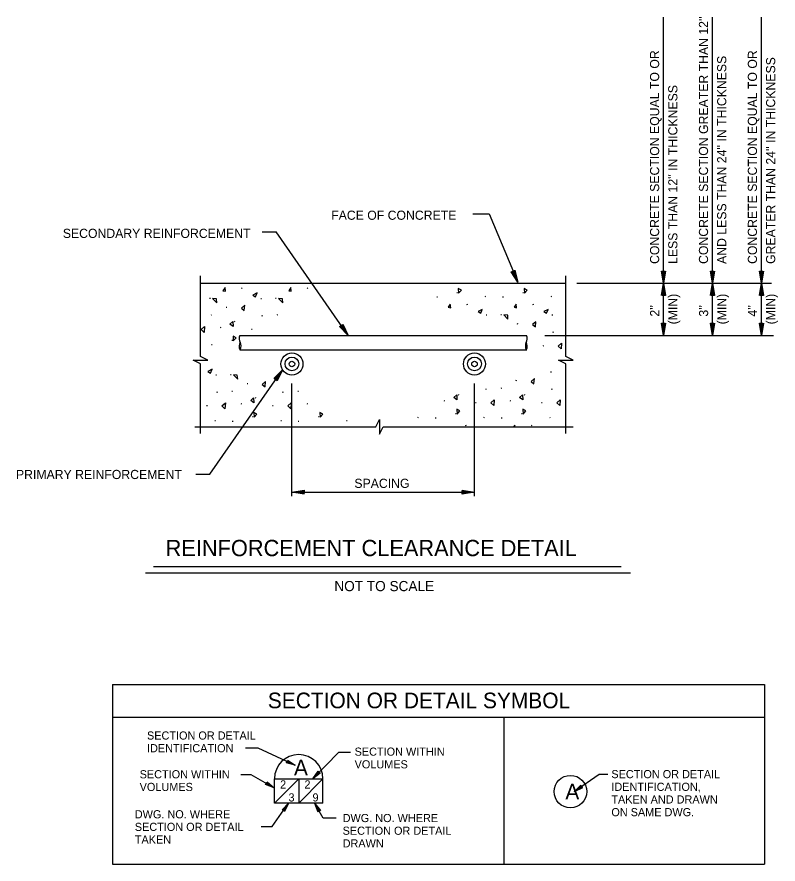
# Model space of a CAD drawing. Extents: x 22369.62 to 22376.4, y 22369.62 to 22372.46.
# Drawn here: x 22375.429 to 22376.402, y 22369.902 to 22370.985 of the extents above; entities that cross this region are included whole.
import ezdxf

# ---------------------------------------------------------------- set-up
doc = ezdxf.new("R2010")
doc.units = 0
for name, color, linetype in [('Default', 7, 'Continuous'), ('Level 1', 7, 'Continuous'), ('Level 10', 7, 'Continuous'), ('Level 2', 7, 'Continuous'), ('Level 22', 7, 'Continuous'), ('Level 3', 7, 'Continuous'), ('Level 4', 7, 'Continuous'), ('Level 50', 7, 'Continuous'), ('Level 7', 7, 'Continuous'), ('Level 8', 7, 'Continuous')]:
    doc.layers.add(name, color=color, linetype=linetype)

msp = doc.modelspace()

# ---------------------------------------------------------------- linework, layer by layer
at = {"layer": 'Default'}
for p, q in [((22375.7173, 22370.6384), (22375.7163, 22370.6379)), ((22375.8014, 22370.6384), (22375.8004, 22370.6379)), ((22375.967, 22370.6265), (22375.9659, 22370.6265)), ((22375.9927, 22370.6321), (22375.9918, 22370.6322)), ((22376.0288, 22370.6272), (22376.0279, 22370.6274)), ((22376.0512, 22370.6265), (22376.0501, 22370.6265)), ((22376.0768, 22370.6321), (22376.076, 22370.6322)), ((22376.1129, 22370.6272), (22376.1121, 22370.6274)), ((22375.6767, 22370.625), (22375.6756, 22370.625)), ((22375.7422, 22370.6246), (22375.7411, 22370.6246)), ((22375.7609, 22370.625), (22375.7598, 22370.625)), ((22376.0052, 22370.6174), (22376.0042, 22370.6169)), ((22376.0894, 22370.6174), (22376.0884, 22370.6169)), ((22375.6979, 22370.6133), (22375.6968, 22370.6135)), ((22375.6783, 22370.6039), (22375.6775, 22370.6036)), ((22375.7085, 22370.5951), (22375.7076, 22370.5956)), ((22375.7431, 22370.6028), (22375.742, 22370.6025)), ((22375.7625, 22370.6039), (22375.7617, 22370.6036)), ((22376.0301, 22370.6036), (22376.029, 22370.6036)), ((22376.0488, 22370.604), (22376.0477, 22370.604)), ((22376.1143, 22370.6036), (22376.1132, 22370.6036)), ((22375.6904, 22370.5873), (22375.6895, 22370.5877)), ((22375.7303, 22370.5853), (22375.7294, 22370.5852)), ((22376.07, 22370.5923), (22376.0689, 22370.5925)), ((22376.1152, 22370.5818), (22376.1141, 22370.5815)), ((22375.6791, 22370.5656), (22375.678, 22370.5656)), ((22375.7048, 22370.5711), (22375.7039, 22370.5712)), ((22376.1024, 22370.5643), (22376.1015, 22370.5642)), ((22376.1125, 22370.531), (22376.1114, 22370.531)), ((22376.1309, 22370.5314), (22376.1301, 22370.5314)), ((22375.6847, 22370.527), (22375.6835, 22370.527)), ((22375.7033, 22370.5274), (22375.7023, 22370.5274)), ((22376.0682, 22370.5198), (22376.0671, 22370.52)), ((22375.7245, 22370.5158), (22375.7235, 22370.516)), ((22376.0292, 22370.5092), (22376.0281, 22370.5089)), ((22376.0486, 22370.5103), (22376.0478, 22370.51)), ((22376.1134, 22370.5092), (22376.1123, 22370.5089)), ((22375.6856, 22370.5052), (22375.6844, 22370.5049)), ((22375.705, 22370.5063), (22375.7042, 22370.506)), ((22375.7351, 22370.4975), (22375.7342, 22370.4981)), ((22375.7697, 22370.5052), (22375.7686, 22370.5049)), ((22375.7891, 22370.5063), (22375.7883, 22370.506)), ((22375.9946, 22370.5015), (22375.9937, 22370.5021)), ((22376.0788, 22370.5015), (22376.0779, 22370.5021)), ((22375.6728, 22370.4878), (22375.6719, 22370.4877)), ((22375.717, 22370.4898), (22375.7161, 22370.4902)), ((22375.757, 22370.4878), (22375.7561, 22370.4877)), ((22375.8012, 22370.4898), (22375.8003, 22370.4902)), ((22375.9765, 22370.4938), (22375.9756, 22370.4942)), ((22376.0165, 22370.4918), (22376.0155, 22370.4917)), ((22376.0606, 22370.4938), (22376.0598, 22370.4942)), ((22376.1006, 22370.4918), (22376.0997, 22370.4917)), ((22375.9909, 22370.4776), (22375.99, 22370.4776)), ((22376.075, 22370.4776), (22376.0742, 22370.4776)), ((22375.6833, 22370.4687), (22375.6825, 22370.4688)), ((22375.7058, 22370.468), (22375.7046, 22370.468)), ((22375.7314, 22370.4736), (22375.7306, 22370.4736)), ((22375.7675, 22370.4687), (22375.7667, 22370.4688)), ((22375.7899, 22370.468), (22375.7888, 22370.468)), ((22375.8156, 22370.4736), (22375.8147, 22370.4736)), ((22375.8517, 22370.4687), (22375.8508, 22370.4688)), ((22375.9428, 22370.4727), (22375.942, 22370.4728)), ((22375.9652, 22370.472), (22375.9641, 22370.472)), ((22376.027, 22370.4727), (22376.0261, 22370.4728)), ((22376.0494, 22370.472), (22376.0483, 22370.472)), ((22376.1111, 22370.4727), (22376.1103, 22370.4728)), ((22376.0034, 22370.4629), (22376.0024, 22370.4624)), ((22376.0876, 22370.4629), (22376.0866, 22370.4624))]:
    msp.add_line(p, q, dxfattribs=at)
for points in [[(22375.6959, 22370.6342), (22375.6954, 22370.6388), (22375.6928, 22370.6349)], [(22375.7801, 22370.6342), (22375.7795, 22370.6388), (22375.777, 22370.6349)], [(22375.9939, 22370.6318), (22375.9974, 22370.6358), (22375.9935, 22370.6379)], [(22376.0781, 22370.6318), (22376.0816, 22370.6358), (22376.0776, 22370.6379)], [(22375.7343, 22370.627), (22375.7363, 22370.6321), (22375.7308, 22370.6294)], [(22375.6845, 22370.6247), (22375.6795, 22370.625), (22375.6849, 22370.6194)], [(22375.7207, 22370.6163), (22375.7164, 22370.6126), (22375.7199, 22370.6096)], [(22375.7687, 22370.6247), (22375.7637, 22370.625), (22375.7691, 22370.6194)], [(22375.9839, 22370.6132), (22375.9833, 22370.6178), (22375.9807, 22370.6139)], [(22376.068, 22370.6132), (22376.0674, 22370.6178), (22376.0649, 22370.6139)], [(22376.0222, 22370.606), (22376.0242, 22370.6111), (22376.0187, 22370.6084)], [(22376.1064, 22370.606), (22376.1084, 22370.6111), (22376.1029, 22370.6084)], [(22375.7056, 22370.5892), (22375.7016, 22370.5922), (22375.7054, 22370.5956)], [(22376.0566, 22370.6037), (22376.0516, 22370.604), (22376.057, 22370.5984)], [(22376.0927, 22370.5953), (22376.0885, 22370.5916), (22376.092, 22370.5886)], [(22375.6687, 22370.5817), (22375.6648, 22370.5852), (22375.6691, 22370.589)], [(22375.706, 22370.5708), (22375.7095, 22370.5748), (22375.7056, 22370.577)], [(22376.1249, 22370.5607), (22376.1211, 22370.5642), (22376.1254, 22370.568)], [(22375.6768, 22370.5295), (22375.6788, 22370.5346), (22375.6733, 22370.5319)], [(22375.7111, 22370.5272), (22375.7061, 22370.5274), (22375.7116, 22370.5219)], [(22375.7473, 22370.5188), (22375.743, 22370.5151), (22375.7466, 22370.5121)], [(22376.0909, 22370.5228), (22376.0867, 22370.519), (22376.0902, 22370.5161)], [(22375.7322, 22370.4916), (22375.7282, 22370.4946), (22375.732, 22370.498)], [(22375.9917, 22370.4956), (22375.9877, 22370.4986), (22375.9915, 22370.502)], [(22376.0758, 22370.4956), (22376.0718, 22370.4986), (22376.0757, 22370.502)], [(22375.6953, 22370.4841), (22375.6915, 22370.4877), (22375.6958, 22370.4915)], [(22375.7795, 22370.4841), (22375.7756, 22370.4877), (22375.7799, 22370.4915)], [(22376.039, 22370.4881), (22376.0351, 22370.4916), (22376.0394, 22370.4955)], [(22376.1231, 22370.4881), (22376.1193, 22370.4916), (22376.1236, 22370.4955)], [(22375.7326, 22370.4733), (22375.7362, 22370.4773), (22375.7322, 22370.4794)], [(22375.8168, 22370.4733), (22375.8203, 22370.4773), (22375.8164, 22370.4794)], [(22375.9921, 22370.4773), (22375.9956, 22370.4813), (22375.9917, 22370.4834)], [(22376.0763, 22370.4773), (22376.0798, 22370.4813), (22376.0758, 22370.4834)]]:
    msp.add_lwpolyline(points, close=True, dxfattribs=at)
msp.add_lwpolyline([(22376.0659, 22370.4609), (22376.0656, 22370.4632), (22376.0641, 22370.4609)], dxfattribs=at)
at = {"layer": 'Level 1'}
for p, q in [((22376.2559, 22370.6444), (22376.2559, 22370.9842)), ((22376.3184, 22370.6444), (22376.3184, 22370.9842)), ((22376.3809, 22370.6444), (22376.3809, 22370.9842)), ((22376.3809, 22370.6444), (22376.3809, 22370.7294)), ((22375.6642, 22370.5508), (22375.6642, 22370.6541)), ((22376.1309, 22370.5508), (22376.1309, 22370.6541)), ((22376.145, 22370.6444), (22376.3938, 22370.6444)), ((22376.2559, 22370.5777), (22376.2559, 22370.6444)), ((22376.3184, 22370.5777), (22376.3184, 22370.6444)), ((22376.3809, 22370.5777), (22376.3809, 22370.6444)), ((22376.1039, 22370.5777), (22376.3962, 22370.5777)), ((22375.6736, 22370.5461), (22375.6642, 22370.5508)), ((22376.1402, 22370.5461), (22376.1309, 22370.5508)), ((22375.6642, 22370.5415), (22375.6548, 22370.5461)), ((22375.6548, 22370.5461), (22375.6736, 22370.5461)), ((22375.6642, 22370.4527), (22375.6642, 22370.5415)), ((22376.1309, 22370.5415), (22376.1215, 22370.5461)), ((22376.1215, 22370.5461), (22376.1402, 22370.5461)), ((22376.1309, 22370.4527), (22376.1309, 22370.5415)), ((22375.7809, 22370.3725), (22375.7809, 22370.5164)), ((22376.0142, 22370.3725), (22376.0142, 22370.5164)), ((22375.888, 22370.4611), (22375.8927, 22370.4704)), ((22375.8927, 22370.4704), (22375.8927, 22370.4517)), ((22375.6569, 22370.4611), (22375.888, 22370.4611)), ((22375.8927, 22370.4517), (22375.8974, 22370.4611)), ((22375.8974, 22370.4611), (22376.1401, 22370.4611)), ((22375.7809, 22370.3777), (22376.0142, 22370.3777)), ((22375.7823, 22370.0301), (22375.7823, 22370.0301)), ((22375.7852, 22370.0288), (22375.7852, 22370.0288)), ((22375.8076, 22370.0115), (22375.8076, 22370.0115)), ((22375.8099, 22370.0138), (22375.8099, 22370.0138)), ((22375.7555, 22370.0016), (22375.7555, 22370.0016)), ((22375.7584, 22370), (22375.7584, 22370)), ((22376.1415, 22369.9949), (22376.1415, 22369.9949)), ((22376.1442, 22369.9968), (22376.1442, 22369.9968)), ((22375.7747, 22369.9777), (22375.7747, 22369.9777)), ((22375.7766, 22369.9804), (22375.7766, 22369.9804)), ((22375.8101, 22369.9799), (22375.8101, 22369.9799)), ((22375.8117, 22369.9771), (22375.8117, 22369.9771))]:
    msp.add_line(p, q, dxfattribs=at)
for points in [[(22375.7214, 22370.0509), (22375.7373, 22370.0509), (22375.7852, 22370.0288)], [(22375.8558, 22370.0451), (22375.8405, 22370.0451), (22375.8076, 22370.0115)], [(22375.7754, 22370.0354), (22375.7852, 22370.0288), (22375.7738, 22370.0319), (22375.7752, 22370.0349), (22375.7823, 22370.0301), (22375.7745, 22370.0323), (22375.7754, 22370.0342), (22375.7794, 22370.0315), (22375.7752, 22370.0326), (22375.7756, 22370.0334), (22375.7765, 22370.0328)], [(22375.8172, 22370.0185), (22375.8076, 22370.0115), (22375.8144, 22370.0212), (22375.8168, 22370.0189), (22375.8099, 22370.0138), (22375.8145, 22370.0204), (22375.816, 22370.0189), (22375.8121, 22370.0161), (22375.8146, 22370.0196), (22375.8152, 22370.019), (22375.8143, 22370.0184)], [(22375.7156, 22370.0169), (22375.7283, 22370.0169), (22375.7584, 22370)], [(22376.1845, 22370.017), (22376.1736, 22370.017), (22376.1415, 22369.9949)], [(22375.7491, 22370.0074), (22375.7584, 22370), (22375.7472, 22370.004), (22375.7489, 22370.0069), (22375.7555, 22370.0016), (22375.748, 22370.0043), (22375.749, 22370.0062), (22375.7528, 22370.0031), (22375.7487, 22370.0046), (22375.7491, 22370.0054), (22375.75, 22370.0047)], [(22376.1523, 22370), (22376.1415, 22369.9949), (22376.1501, 22370.0032), (22376.152, 22370.0004), (22376.1442, 22369.9968), (22376.15, 22370.0024), (22376.1512, 22370.0006), (22376.1468, 22369.9986), (22376.15, 22370.0016), (22376.1505, 22370.0009), (22376.1495, 22370.0004)], [(22375.7417, 22369.9504), (22375.7558, 22369.9504), (22375.7766, 22369.9804)], [(22375.7683, 22369.9719), (22375.7766, 22369.9804), (22375.7715, 22369.9697), (22375.7688, 22369.9716), (22375.7747, 22369.9777), (22375.7713, 22369.9705), (22375.7695, 22369.9717), (22375.773, 22369.9752), (22375.7711, 22369.9712), (22375.7703, 22369.9717), (22375.7711, 22369.9725)], [(22375.8374, 22369.9613), (22375.8208, 22369.9613), (22375.8101, 22369.9799)], [(22375.8143, 22369.9688), (22375.8101, 22369.9799), (22375.8176, 22369.9707), (22375.8147, 22369.9691), (22375.8117, 22369.9771), (22375.8168, 22369.9708), (22375.815, 22369.9698), (22375.8133, 22369.9744), (22375.816, 22369.9709), (22375.8153, 22369.9705), (22375.8149, 22369.9715)]]:
    msp.add_lwpolyline(points, dxfattribs=at)
at = {"layer": 'Level 10'}
for p, q in [((22375.6642, 22370.6444), (22376.1309, 22370.6444)), ((22375.604, 22370.2825), (22376.2016, 22370.2825)), ((22375.5938, 22370.2747), (22376.2136, 22370.2747)), ((22375.5515, 22370.1317), (22375.5515, 22369.9025)), ((22375.5515, 22370.1317), (22376.3848, 22370.1317)), ((22376.3848, 22370.1317), (22376.3848, 22369.9025)), ((22375.5515, 22370.09), (22376.3848, 22370.09)), ((22376.0515, 22370.09), (22376.0515, 22369.9025)), ((22375.5515, 22369.9025), (22376.3848, 22369.9025))]:
    msp.add_line(p, q, dxfattribs=at)
at = {"layer": 'Level 2'}
for p, q in [((22375.7429, 22370.7101), (22375.7608, 22370.7101)), ((22375.8529, 22370.5777), (22375.7608, 22370.7101)), ((22375.676, 22370.4005), (22375.7689, 22370.5339)), ((22375.6581, 22370.4005), (22375.676, 22370.4005))]:
    msp.add_line(p, q, dxfattribs=at)
for points in [[(22376.012, 22370.7329), (22376.0328, 22370.7329), (22376.0696, 22370.6456)], [(22376.0659, 22370.661), (22376.0696, 22370.6456), (22376.0611, 22370.659), (22376.0652, 22370.6607), (22376.0679, 22370.6496), (22376.0622, 22370.6587), (22376.0648, 22370.6598), (22376.0663, 22370.6534), (22376.0632, 22370.6584), (22376.0643, 22370.6588), (22376.0646, 22370.6574)], [(22376.2584, 22370.66), (22376.2559, 22370.6444), (22376.2533, 22370.66), (22376.2577, 22370.66), (22376.2559, 22370.6487), (22376.2541, 22370.6593), (22376.2569, 22370.6593), (22376.2559, 22370.6529), (22376.2549, 22370.6586), (22376.2561, 22370.6586), (22376.2559, 22370.6572)], [(22376.3209, 22370.66), (22376.3184, 22370.6444), (22376.3158, 22370.66), (22376.3202, 22370.66), (22376.3184, 22370.6487), (22376.3166, 22370.6593), (22376.3194, 22370.6593), (22376.3184, 22370.6529), (22376.3174, 22370.6586), (22376.3186, 22370.6586), (22376.3184, 22370.6572)], [(22376.3834, 22370.66), (22376.3809, 22370.6444), (22376.3783, 22370.66), (22376.3827, 22370.66), (22376.3809, 22370.6487), (22376.3791, 22370.6593), (22376.3819, 22370.6593), (22376.3809, 22370.6529), (22376.3799, 22370.6586), (22376.3811, 22370.6586), (22376.3809, 22370.6572)], [(22376.2533, 22370.6288), (22376.2559, 22370.6444), (22376.2584, 22370.6288), (22376.254, 22370.6288), (22376.2559, 22370.6401), (22376.2576, 22370.6295), (22376.2548, 22370.6295), (22376.2559, 22370.6359), (22376.2568, 22370.6301), (22376.2556, 22370.6301), (22376.2559, 22370.6316)], [(22376.3158, 22370.6288), (22376.3184, 22370.6444), (22376.3209, 22370.6288), (22376.3165, 22370.6288), (22376.3184, 22370.6401), (22376.3201, 22370.6295), (22376.3173, 22370.6295), (22376.3184, 22370.6359), (22376.3193, 22370.6301), (22376.3181, 22370.6301), (22376.3184, 22370.6316)], [(22376.3783, 22370.6288), (22376.3809, 22370.6444), (22376.3834, 22370.6288), (22376.379, 22370.6288), (22376.3809, 22370.6401), (22376.3826, 22370.6295), (22376.3798, 22370.6295), (22376.3809, 22370.6359), (22376.3818, 22370.6301), (22376.3806, 22370.6301), (22376.3809, 22370.6316)], [(22375.8461, 22370.592), (22375.8529, 22370.5777), (22375.8419, 22370.589), (22375.8455, 22370.5916), (22375.8504, 22370.5813), (22375.8429, 22370.589), (22375.8453, 22370.5906), (22375.848, 22370.5847), (22375.844, 22370.5889), (22375.8449, 22370.5896), (22375.8456, 22370.5883)], [(22376.2584, 22370.5933), (22376.2559, 22370.5777), (22376.2533, 22370.5933), (22376.2577, 22370.5933), (22376.2559, 22370.5821), (22376.2541, 22370.5926), (22376.2569, 22370.5926), (22376.2559, 22370.5862), (22376.2549, 22370.592), (22376.2561, 22370.592), (22376.2559, 22370.5906)], [(22376.3209, 22370.5933), (22376.3184, 22370.5777), (22376.3158, 22370.5933), (22376.3202, 22370.5933), (22376.3184, 22370.5821), (22376.3166, 22370.5926), (22376.3194, 22370.5926), (22376.3184, 22370.5862), (22376.3174, 22370.592), (22376.3186, 22370.592), (22376.3184, 22370.5906)], [(22376.3834, 22370.5933), (22376.3809, 22370.5777), (22376.3783, 22370.5933), (22376.3827, 22370.5933), (22376.3809, 22370.5821), (22376.3791, 22370.5926), (22376.3819, 22370.5926), (22376.3809, 22370.5862), (22376.3799, 22370.592), (22376.3811, 22370.592), (22376.3809, 22370.5906)], [(22375.7579, 22370.5226), (22375.7689, 22370.5339), (22375.7621, 22370.5197), (22375.7585, 22370.5222), (22375.7664, 22370.5304), (22375.7618, 22370.5207), (22375.7595, 22370.5223), (22375.764, 22370.527), (22375.7615, 22370.5217), (22375.7606, 22370.5224), (22375.7616, 22370.5234)], [(22375.7964, 22370.3751), (22375.7809, 22370.3777), (22375.7964, 22370.3803), (22375.7964, 22370.3759), (22375.7852, 22370.3777), (22375.7958, 22370.3795), (22375.7958, 22370.3766), (22375.7894, 22370.3777), (22375.7951, 22370.3786), (22375.7951, 22370.3775), (22375.7937, 22370.3777)], [(22375.9986, 22370.3803), (22376.0142, 22370.3777), (22375.9986, 22370.3751), (22375.9986, 22370.3796), (22376.0099, 22370.3777), (22375.9993, 22370.376), (22375.9993, 22370.3788), (22376.0057, 22370.3777), (22375.9999, 22370.3768), (22375.9999, 22370.378), (22376.0014, 22370.3777)]]:
    msp.add_lwpolyline(points, dxfattribs=at)
at = {"layer": 'Level 22'}
for centre, radius in [((22375.7809, 22370.5413), 0.0141), ((22376.0142, 22370.5413), 0.0141), ((22375.7809, 22370.5413), 0.00879), ((22375.7809, 22370.5413), 0.00352), ((22376.0142, 22370.5413), 0.00879), ((22376.0142, 22370.5413), 0.00352)]:
    msp.add_circle(centre, radius, dxfattribs=at)
at = {"layer": 'Level 3'}
for p, q in [((22375.7586, 22370.0114), (22375.8206, 22370.0114)), ((22375.7586, 22369.9804), (22375.7586, 22370.0114)), ((22375.7896, 22370.0114), (22375.7896, 22369.9804)), ((22375.8206, 22369.9804), (22375.8206, 22370.0114)), ((22375.8206, 22369.9804), (22375.7586, 22369.9804))]:
    msp.add_line(p, q, dxfattribs=at)
msp.add_circle((22376.1368, 22369.995), 0.0208, dxfattribs=at)
msp.add_arc((22375.7896, 22370.0114), 0.031, 0, 180, dxfattribs=at)
at = {"layer": 'Level 50'}
for p, q in [((22375.7586, 22369.9804), (22375.7896, 22370.0114)), ((22375.7896, 22369.9804), (22375.8206, 22370.0114))]:
    msp.add_line(p, q, dxfattribs=at)
at = {"layer": 'Level 7'}
for p, q in [((22375.7142, 22370.5777), (22376.0809, 22370.5777)), ((22375.7147, 22370.5594), (22376.0809, 22370.5594))]:
    msp.add_line(p, q, dxfattribs=at)
for centre, radius, start, end in [((22375.7248, 22370.5738), 0.0113, 159.8081, 206.6071), ((22376.0702, 22370.5738), 0.0113, 333.3929, 20.1919), ((22375.7248, 22370.5637), 0.0113, 153.3929, 200.1936), ((22375.7046, 22370.5637), 0.0113, 339.8064, 26.6071), ((22376.0905, 22370.5637), 0.0113, 153.3929, 200.1936), ((22376.0702, 22370.5637), 0.0113, 339.8064, 26.6071), ((22375.7147, 22370.5599), 0.000555, 200.1936, 339.8064), ((22376.0803, 22370.5599), 0.000555, 200.1936, 339.8064)]:
    msp.add_arc(centre, radius, start, end, dxfattribs=at)
at = {"layer": 'Level 8'}
for p, q in [((22376.0679, 22370.6496), (22376.0679, 22370.6496)), ((22376.2559, 22370.6487), (22376.2559, 22370.6487)), ((22376.3184, 22370.6487), (22376.3184, 22370.6487)), ((22376.3809, 22370.6487), (22376.3809, 22370.6487)), ((22376.0696, 22370.6456), (22376.0696, 22370.6456)), ((22376.2559, 22370.6444), (22376.2559, 22370.6444)), ((22376.2559, 22370.6444), (22376.2559, 22370.6444)), ((22376.2559, 22370.6401), (22376.2559, 22370.6401)), ((22376.3184, 22370.6444), (22376.3184, 22370.6444)), ((22376.3184, 22370.6444), (22376.3184, 22370.6444)), ((22376.3184, 22370.6401), (22376.3184, 22370.6401)), ((22376.3809, 22370.6444), (22376.3809, 22370.6444)), ((22376.3809, 22370.6444), (22376.3809, 22370.6444)), ((22376.3809, 22370.6401), (22376.3809, 22370.6401)), ((22375.8504, 22370.5813), (22375.8504, 22370.5813)), ((22375.8529, 22370.5777), (22375.8529, 22370.5777)), ((22376.2559, 22370.5821), (22376.2559, 22370.5821)), ((22376.2559, 22370.5777), (22376.2559, 22370.5777)), ((22376.3184, 22370.5821), (22376.3184, 22370.5821)), ((22376.3184, 22370.5777), (22376.3184, 22370.5777)), ((22376.3809, 22370.5821), (22376.3809, 22370.5821)), ((22376.3809, 22370.5777), (22376.3809, 22370.5777)), ((22375.7664, 22370.5304), (22375.7664, 22370.5304)), ((22375.7689, 22370.5339), (22375.7689, 22370.5339)), ((22375.7809, 22370.3777), (22375.7809, 22370.3777)), ((22375.7852, 22370.3777), (22375.7852, 22370.3777)), ((22376.0099, 22370.3777), (22376.0099, 22370.3777)), ((22376.0142, 22370.3777), (22376.0142, 22370.3777))]:
    msp.add_line(p, q, dxfattribs=at)

# ---------------------------------------------------------------- texts
at = {"layer": 'Level 3'}
for s, height, p in [('REINFORCEMENT CLEARANCE DETAIL', 0.020802, (22375.6195, 22370.2958)), ('SECTION OR DETAIL SYMBOL', 0.02, (22375.7501, 22370.1015)), ('A', 0.02, (22375.7835, 22370.0157)), ('A', 0.02, (22376.1303, 22369.985))]:
    msp.add_text(s, height=height, dxfattribs=at).set_placement(p)
at = {"layer": 'Level 4'}
for s, height, p in [("CONCRETE SECTION GREATER THAN 12''", 0.011698, (22376.3127, 22370.6691)), ('CONCRETE SECTION EQUAL TO OR', 0.011698, (22376.2502, 22370.6691)), ('CONCRETE SECTION EQUAL TO OR', 0.011698, (22376.3752, 22370.6691)), ("AND LESS THAN 24'' IN THICKNESS", 0.011698, (22376.336, 22370.6691)), ("GREATER THAN 24'' IN THICKNESS", 0.011698, (22376.3985, 22370.6691)), ("LESS THAN 12'' IN THICKNESS", 0.011698, (22376.2735, 22370.6691)), ('(MIN)', 0.0117, (22376.2736, 22370.5919)), ('(MIN)', 0.0117, (22376.3361, 22370.5919)), ('(MIN)', 0.0117, (22376.3986, 22370.5919)), ("2''", 0.0117, (22376.2503, 22370.6018)), ("3''", 0.0117, (22376.3128, 22370.6018)), ("4''", 0.0117, (22376.3753, 22370.6018))]:
    msp.add_text(s, height=height, rotation=90, dxfattribs=at).set_placement(p)
for s, height, p in [('FACE OF CONCRETE', 0.011698, (22375.8311, 22370.7255)), ('SECONDARY REINFORCEMENT', 0.011698, (22375.4881, 22370.7023)), ('PRIMARY REINFORCEMENT', 0.011698, (22375.4282, 22370.3943)), ('SPACING', 0.0117, (22375.8607, 22370.383)), ('NOT TO SCALE', 0.013, (22375.8351, 22370.2511)), ('SECTION OR DETAIL', 0.010396, (22375.5957, 22370.0615)), ('IDENTIFICATION', 0.010396, (22375.5957, 22370.0453)), ('SECTION WITHIN', 0.010396, (22375.861, 22370.0409)), ('VOLUMES', 0.0104, (22375.861, 22370.0247)), ('SECTION WITHIN', 0.010396, (22375.5863, 22370.012)), ('SECTION OR DETAIL', 0.010396, (22376.1891, 22370.0122)), ('2', 0.0104, (22375.7658, 22369.999)), ('2', 0.0104, (22375.7969, 22369.999)), ('VOLUMES', 0.0104, (22375.5863, 22369.9958)), ('IDENTIFICATION,', 0.010396, (22376.1891, 22369.996)), ('3', 0.0104, (22375.7765, 22369.9824)), ('9', 0.0104, (22375.8072, 22369.9824)), ('TAKEN AND DRAWN', 0.010396, (22376.1891, 22369.9798)), ('DWG. NO. WHERE', 0.010396, (22375.5801, 22369.9609)), ('DWG. NO. WHERE', 0.010396, (22375.8457, 22369.9561)), ('ON SAME DWG.', 0.010396, (22376.1891, 22369.9636)), ('SECTION OR DETAIL', 0.010396, (22375.5801, 22369.9448)), ('SECTION OR DETAIL', 0.010396, (22375.8457, 22369.9399)), ('TAKEN', 0.0104, (22375.5801, 22369.9286)), ('DRAWN', 0.0104, (22375.8457, 22369.9237))]:
    msp.add_text(s, height=height, dxfattribs=at).set_placement(p)

doc.saveas('drawing.dxf')
